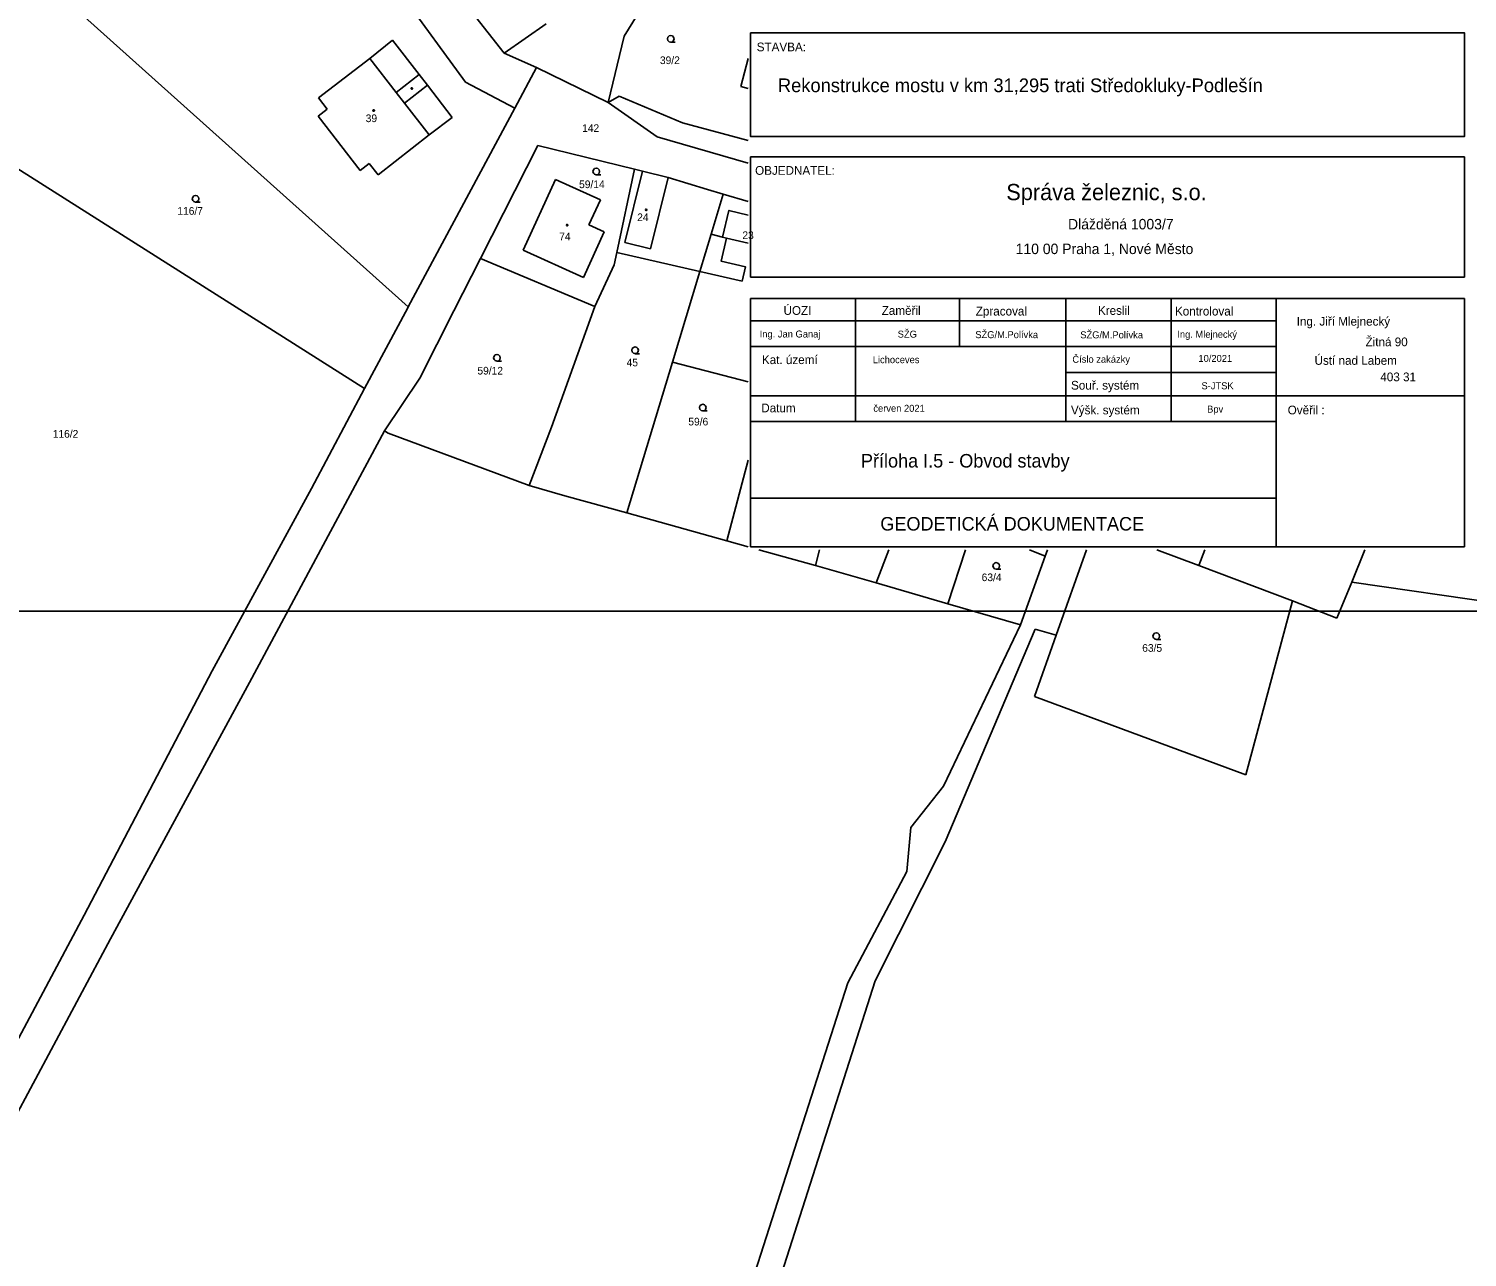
# Model space of a CAD drawing. Extents: x -752343 to -750336, y -1035826 to -1033329.
# Drawn here: x -751691.8 to -751372.1, y -1034703.4 to -1034430.3 of the extents above; entities that cross this region are included whole.
import ezdxf

# ---------------------------------------------------------------- set-up
doc = ezdxf.new("R2010")
doc.units = 0
for name, color, linetype in [('Default', 7, 'Continuous'), ('KN_HRANICE', 7, 'Continuous'), ('KN_KULTURY', 7, 'Continuous'), ('KN_PARCELY', 7, 'Continuous'), ('KN_SLUCKY', 7, 'Continuous'), ('LEGENDA', 7, 'Continuous'), ('tabulka', 7, 'Continuous')]:
    doc.layers.add(name, color=color, linetype=linetype)

# ---------------------------------------------------------------- blocks, each defined once
blk = doc.blocks.new('304')
at = {"layer": 'Default'}
blk.add_lwpolyline([(0, 0), (-0.38, 0.1), (-0.65, 0.37), (-0.75, 0.74), (-0.65, 1.11), (-0.38, 1.38), (-0.01, 1.48), (0.36, 1.38), (0.63, 1.11), (0.73, 0.73), (0.63, 0.35), (0.36, 0.08), (-0.02, -0.02), (0.98, -0.02)], dxfattribs=at)
blk = doc.blocks.new('402')
at = {"layer": 'Default'}
blk.add_lwpolyline([(0.09, 0.15), (0.18, 0), (0.09, -0.15), (-0.09, -0.15), (-0.18, 0), (-0.09, 0.15), (0.09, 0.15)], dxfattribs=at)

msp = doc.modelspace()

# ---------------------------------------------------------------- linework, layer by layer
at = {"layer": 'KN_HRANICE'}
for p, q in [((-751618.73, -1034394.05), (-751586.12, -1034435.76)), ((-751620.28, -1034407.14), (-751594.74, -1034442.18)), ((-751545.55, -1034409.5), (-751559.45, -1034431.95)), ((-751688.64, -1034419.35), (-751607.43, -1034492.1)), ((-751576.79, -1034429.21), (-751586.12, -1034435.76)), ((-751615.98, -1034436.92), (-751610.98, -1034432.81)), ((-751610.98, -1034432.81), (-751605.03, -1034440.5)), ((-751559.45, -1034431.95), (-751563, -1034446.73)), ((-751578.94, -1034438.89), (-751586.12, -1034435.76)), ((-751627.37, -1034445.67), (-751615.98, -1034436.92)), ((-751578.94, -1034438.89), (-751583.78, -1034447.94)), ((-751563, -1034446.73), (-751578.94, -1034438.89)), ((-751533.53, -1034443.11), (-751531.86, -1034436.95)), ((-751605.03, -1034440.5), (-751603.2, -1034442.87)), ((-751594.74, -1034442.18), (-751583.78, -1034447.94)), ((-751627.37, -1034445.67), (-751625.46, -1034448.16)), ((-751603.2, -1034442.87), (-751597.68, -1034450)), ((-751560.58, -1034445.29), (-751563, -1034446.73)), ((-751560.58, -1034445.29), (-751546.49, -1034451.2)), ((-751531.86, -1034443.57), (-751533.53, -1034443.11)), ((-751625.46, -1034448.16), (-751627.48, -1034449.72)), ((-751583.78, -1034447.94), (-751607.43, -1034492.1)), ((-751563, -1034446.73), (-751552.12, -1034454.31)), ((-751627.48, -1034449.72), (-751618.16, -1034461.83)), ((-751597.68, -1034450), (-751602.8, -1034453.9)), ((-751546.49, -1034451.2), (-751531.86, -1034455.16)), ((-751614.11, -1034462.79), (-751602.8, -1034453.9)), ((-751552.12, -1034454.31), (-751531.86, -1034460.15)), ((-751617.15, -1034510.28), (-751700.27, -1034457.61)), ((-751578.63, -1034456.23), (-751591.42, -1034481.41)), ((-751557.12, -1034461.54), (-751578.63, -1034456.23)), ((-751618.16, -1034461.83), (-751616.1, -1034460.25)), ((-751616.1, -1034460.25), (-751614.11, -1034462.79)), ((-751557.12, -1034461.54), (-751561.07, -1034480.02)), ((-751555.41, -1034461.96), (-751557.12, -1034461.54)), ((-751574.75, -1034463.78), (-751581.87, -1034479.49)), ((-751564.73, -1034468.32), (-751574.75, -1034463.78)), ((-751549.7, -1034463.37), (-751555.41, -1034461.96)), ((-751540.9, -1034466.02), (-751549.7, -1034463.37)), ((-751537.45, -1034467.09), (-751540.9, -1034466.02)), ((-751540.14, -1034475.99), (-751537.45, -1034467.09)), ((-751531.86, -1034468.69), (-751537.45, -1034467.09)), ((-751567.27, -1034473.92), (-751564.73, -1034468.32)), ((-751563.9, -1034475.45), (-751567.27, -1034473.92)), ((-751568.48, -1034485.56), (-751563.9, -1034475.45)), ((-751542.64, -1034484.25), (-751540.14, -1034475.99)), ((-751581.87, -1034479.49), (-751568.48, -1034485.56)), ((-751561.66, -1034482.75), (-751561.07, -1034480.02)), ((-751561.07, -1034480.02), (-751542.64, -1034484.25)), ((-751591.42, -1034481.41), (-751597.29, -1034492.98)), ((-751591.42, -1034481.41), (-751566, -1034492.05)), ((-751566, -1034492.05), (-751561.66, -1034482.75)), ((-751548.74, -1034504.43), (-751542.64, -1034484.25)), ((-751607.57, -1034492.37), (-751617.15, -1034510.28)), ((-751607.43, -1034492.1), (-751607.57, -1034492.37)), ((-751597.29, -1034492.98), (-751604.89, -1034507.95)), ((-751575.6, -1034518.88), (-751566, -1034492.05)), ((-751558.88, -1034537.93), (-751548.74, -1034504.43)), ((-751548.74, -1034504.43), (-751531.86, -1034508.79)), ((-751612.74, -1034519.66), (-751604.89, -1034507.95)), ((-751617.15, -1034510.28), (-751628.92, -1034532.53)), ((-751580.59, -1034531.81), (-751575.6, -1034518.88)), ((-751612.74, -1034519.66), (-751642.72, -1034575.65)), ((-751611.9, -1034520.17), (-751612.74, -1034519.66)), ((-751580.59, -1034531.81), (-751611.9, -1034520.17)), ((-751531.86, -1034526.21), (-751536.64, -1034544.11)), ((-751580.59, -1034531.81), (-751572.63, -1034534.09)), ((-751628.92, -1034532.53), (-751651.03, -1034573.04)), ((-751572.63, -1034534.09), (-751558.88, -1034537.93)), ((-751558.88, -1034537.93), (-751536.64, -1034544.11)), ((-751536.64, -1034544.11), (-751531.86, -1034545.44)), ((-751529.49, -1034546.1), (-751516.94, -1034549.6)), ((-751516.05, -1034546.1), (-751516.94, -1034549.6)), ((-751503.46, -1034553.49), (-751500.61, -1034546.1)), ((-751487.48, -1034558.11), (-751483.58, -1034546.1)), ((-751465.87, -1034547.5), (-751471.33, -1034562.81)), ((-751469.34, -1034546.1), (-751465.87, -1034547.5)), ((-751465.37, -1034546.1), (-751465.87, -1034547.5)), ((-751463.42, -1034565.13), (-751456.65, -1034546.1)), ((-751431.72, -1034549.64), (-751441.08, -1034546.1)), ((-751430.35, -1034546.1), (-751431.72, -1034549.64)), ((-751394.78, -1034546.1), (-751397.73, -1034553.31)), ((-751516.94, -1034549.6), (-751503.46, -1034553.49)), ((-751410.9, -1034557.5), (-751431.72, -1034549.64)), ((-751503.46, -1034553.49), (-751487.48, -1034558.11)), ((-751401.02, -1034561.34), (-751397.73, -1034553.31)), ((-751397.73, -1034553.31), (-751272.79, -1034571.27)), ((-751421.27, -1034596.11), (-751410.9, -1034557.5)), ((-751410.9, -1034557.5), (-751401.02, -1034561.34)), ((-751487.48, -1034558.11), (-751471.33, -1034562.81)), ((-751471.33, -1034562.81), (-751488.49, -1034598.68)), ((-751488.09, -1034611.04), (-751468.06, -1034563.8)), ((-751468.06, -1034563.8), (-751463.42, -1034565.13)), ((-751463.42, -1034565.13), (-751468.26, -1034578.75)), ((-751651.03, -1034573.04), (-751679.5, -1034627.36)), ((-751673.63, -1034632.56), (-751642.72, -1034575.65)), ((-751468.26, -1034578.75), (-751421.27, -1034596.11)), ((-751488.49, -1034598.68), (-751495.75, -1034607.86)), ((-751495.75, -1034607.86), (-751496.62, -1034617.62)), ((-751488.09, -1034611.04), (-751503.64, -1034641.95)), ((-751496.62, -1034617.62), (-751509.71, -1034642.36)), ((-751679.5, -1034627.36), (-751713.81, -1034691.67)), ((-751706.96, -1034694.92), (-751673.63, -1034632.56)), ((-751551.55, -1034772.77), (-751509.71, -1034642.36)), ((-751503.64, -1034641.95), (-751545.07, -1034771.46))]:
    msp.add_line(p, q, dxfattribs=at)
at = {"layer": 'KN_SLUCKY'}
for p, q in [((-751610.13, -1034444.45), (-751615.98, -1034436.92)), ((-751610.13, -1034444.45), (-751605.03, -1034440.5)), ((-751608.29, -1034446.82), (-751610.13, -1034444.45)), ((-751608.29, -1034446.82), (-751603.2, -1034442.87)), ((-751602.8, -1034453.9), (-751608.29, -1034446.82)), ((-751559.33, -1034477.82), (-751555.41, -1034461.96)), ((-751553.62, -1034479.23), (-751549.7, -1034463.37)), ((-751537.6, -1034476.61), (-751540.14, -1034475.99)), ((-751536.74, -1034476.82), (-751537.6, -1034476.61)), ((-751559.33, -1034477.82), (-751553.62, -1034479.23)), ((-751542.64, -1034484.25), (-751533.23, -1034486.41))]:
    msp.add_line(p, q, dxfattribs=at)
for points in [[(-751531.86, -1034471.72), (-751536.17, -1034470.68), (-751537.6, -1034476.61)], [(-751533.23, -1034486.41), (-751532.5, -1034483.19), (-751537.92, -1034481.95), (-751536.74, -1034476.82)], [(-751531.86, -1034478), (-751536.74, -1034476.82)]]:
    msp.add_lwpolyline(points, dxfattribs=at)
at = {"layer": 'LEGENDA'}
msp.add_lwpolyline([(-751353.18, -1034559.75), (-751947.18, -1034559.75), (-751947.18, -1034139.75), (-751353.18, -1034139.75)], close=True, dxfattribs=at)
at = {"layer": 'tabulka'}
for p, q in [((-751531.34, -1034490.3), (-751372.68, -1034490.3)), ((-751508.05, -1034490.3), (-751508.05, -1034517.62)), ((-751484.9, -1034490.3), (-751484.9, -1034500.92)), ((-751461.3, -1034490.3), (-751461.3, -1034517.62)), ((-751437.85, -1034490.3), (-751437.85, -1034517.62)), ((-751414.55, -1034545.43), (-751414.55, -1034490.3)), ((-751531.34, -1034495.2), (-751414.55, -1034495.2)), ((-751531.34, -1034500.92), (-751414.55, -1034500.92)), ((-751461.3, -1034506.73), (-751414.55, -1034506.73)), ((-751531.34, -1034511.92), (-751372.68, -1034511.92)), ((-751531.34, -1034517.62), (-751414.55, -1034517.62)), ((-751531.34, -1034534.61), (-751414.55, -1034534.61))]:
    msp.add_line(p, q, dxfattribs=at)
for points in [[(-751531.34, -1034431.21), (-751372.68, -1034431.21), (-751372.68, -1034454.27), (-751531.34, -1034454.27)], [(-751531.34, -1034458.79), (-751372.68, -1034458.79), (-751372.68, -1034485.49), (-751531.34, -1034485.49)]]:
    msp.add_lwpolyline(points, close=True, dxfattribs=at)
msp.add_lwpolyline([(-751372.68, -1034490.3), (-751372.68, -1034545.43), (-751531.34, -1034545.43), (-751531.34, -1034490.3)], dxfattribs=at)

# ---------------------------------------------------------------- block references
at = {"layer": 'KN_KULTURY'}
for name, p in [('304', (-751549.09, -1034433.29)), ('402', (-751606.66, -1034443.56)), ('402', (-751615.12, -1034448.48)), ('304', (-751565.64, -1034462.75)), ('304', (-751654.71, -1034468.82)), ('402', (-751554.56, -1034470.55)), ('402', (-751572.11, -1034473.96)), ('304', (-751587.71, -1034504.18)), ('304', (-751557.03, -1034502.51)), ('304', (-751541.99, -1034515.25)), ('304', (-751476.73, -1034550.44)), ('304', (-751441.16, -1034566.03))]:
    msp.add_blockref(name, p, dxfattribs=at)

# ---------------------------------------------------------------- texts
at = {"layer": 'KN_PARCELY'}
for s, p in [('39/2', (-751551.5, -1034438.16)), ('39', (-751616.9, -1034451.06)), ('142', (-751568.8, -1034453.25)), ('59/14', (-751569.47, -1034465.73)), ('116/7', (-751658.77, -1034471.65)), ('24', (-751556.56, -1034473.06)), ('74', (-751573.89, -1034477.33)), ('23', (-751533.17, -1034477.05)), ('59/12', (-751592.07, -1034507.16)), ('45', (-751558.91, -1034505.34)), ('59/6', (-751545.19, -1034518.48)), ('116/2', (-751686.47, -1034521.21)), ('63/4', (-751479.99, -1034553.09)), ('63/5', (-751444.3, -1034568.79))]:
    msp.add_text(s, height=1.7, dxfattribs=at).set_placement(p)
at = {"layer": 'tabulka'}
for s, height, p in [('STAVBA:', 1.94, (-751529.99, -1034435.32)), ('Rekonstrukce mostu v km 31,295 trati Středokluky-Podlešín', 3.04, (-751525.27, -1034444.4)), ('OBJEDNATEL:', 1.94, (-751530.35, -1034462.77)), ('Správa železnic, s.o.', 3.61, (-751474.51, -1034468.41)), ('Dlážděná 1003/7', 2.32, (-751460.79, -1034474.9)), ('110 00 Praha 1, Nové Město', 2.32, (-751472.43, -1034480.39)), ('ÚOZI', 1.94, (-751524.03, -1034493.9)), ('Zaměřil', 1.94, (-751502.2, -1034493.9)), ('Zpracoval', 1.94, (-751481.3, -1034494.05)), ('Kreslil', 1.94, (-751454.14, -1034493.9)), ('Kontroloval', 1.94, (-751437.02, -1034494.05)), ('Ing. Jiří Mlejnecký', 1.94, (-751409.96, -1034496.3)), ('Ing. Jan Ganaj', 1.552, (-751529.33, -1034498.93)), ('SŽG', 1.552, (-751498.65, -1034498.96)), ('SŽG/M.Polívka', 1.552, (-751481.4, -1034499.08)), ('SŽG/M.Polívka', 1.552, (-751458.07, -1034499.12)), ('Ing. Mlejnecký', 1.552, (-751436.5, -1034499)), ('Žitná 90', 1.94, (-751394.66, -1034500.88)), ('Kat. území', 1.94, (-751528.84, -1034504.84)), ('Lichoceves', 1.552, (-751504.19, -1034504.64)), ('Číslo zakázky', 1.552, (-751459.82, -1034504.55)), ('10/2021', 1.552, (-751431.81, -1034504.36)), ('Ústí nad Labem', 1.94, (-751406, -1034505)), ('Souř. systém', 1.94, (-751460.12, -1034510.52)), ('S-JTSK', 1.552, (-751431.13, -1034510.44)), ('403 31', 1.94, (-751391.37, -1034508.66)), ('Datum', 1.94, (-751528.98, -1034515.56)), ('červen 2021', 1.552, (-751504.06, -1034515.45)), ('Výšk. systém', 1.94, (-751460.14, -1034516.02)), ('Bpv', 1.552, (-751429.87, -1034515.63)), ('Ověřil :', 1.94, (-751411.96, -1034516.02)), ('Příloha I.5 - Obvod stavby', 3, (-751506.82, -1034527.83)), ('GEODETICKÁ DOKUMENTACE ', 3, (-751502.51, -1034541.84))]:
    msp.add_text(s, height=height, dxfattribs=at).set_placement(p)

doc.saveas('drawing.dxf')
